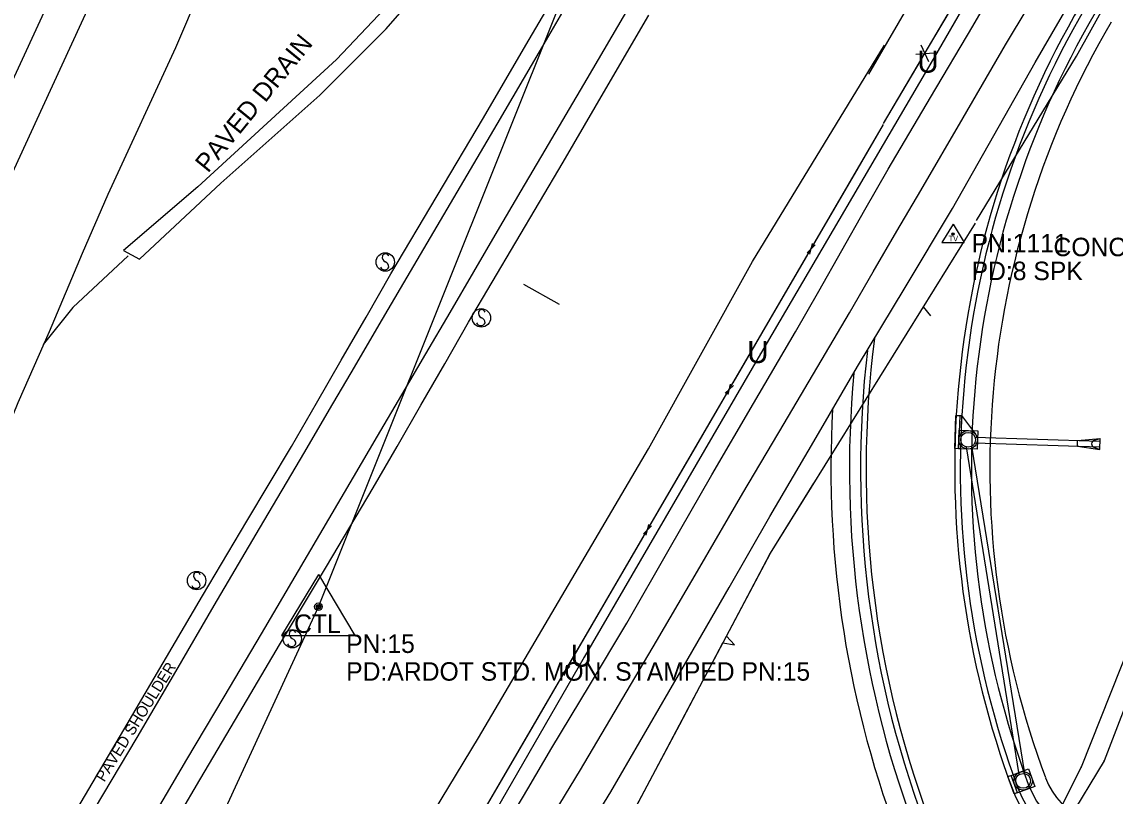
# Model space of a CAD drawing. Extents: x 978516 to 993312, y 1836504 to 1846212.
# Drawn here: x 981447.7 to 981743.5, y 1841810.9 to 1842020.4 of the extents above; entities that cross this region are included whole.
import ezdxf

# ---------------------------------------------------------------- set-up
doc = ezdxf.new("R2010")
doc.units = 0
for name, color, linetype in [('Default', 7, 'Continuous'), ('R_Drainage', 7, 'Continuous'), ('R_Proposed Road', 7, 'Continuous'), ('S_BASELINE', 7, 'Continuous'), ('S_EDGE_PAVEMENT', 7, 'Continuous'), ('S_FENCE', 7, 'Continuous'), ('S_GAS_UTILITIES', 7, 'Continuous'), ('S_PAVEMENT_CROWN', 7, 'Continuous'), ('S_PRIMARY_CTL', 7, 'Continuous'), ('S_PRIMARY_CTL_ANNOT', 7, 'Continuous'), ('S_SECONDARY_CTL', 7, 'Continuous'), ('S_SECONDARY_CTL_ANNOT', 7, 'Continuous'), ('S_SHOULDER', 7, 'Continuous'), ('S_SHOULDER_ANNOT', 7, 'Continuous'), ('S_SIDE_DRAIN_ANNOT', 7, 'Continuous'), ('S_SIGN', 7, 'Continuous'), ('S_STREAM', 7, 'Continuous'), ('S_SURVEY_TEXT_ANNOT', 7, 'Continuous'), ('S_TREE', 7, 'Continuous'), ('S_UNDERGROUND_CABLE', 7, 'Continuous'), ('S_UTL_PT_SYM', 7, 'Continuous'), ('S_WATER_UTILITIES', 7, 'Continuous')]:
    doc.layers.add(name, color=color, linetype=linetype)

msp = doc.modelspace()

# ---------------------------------------------------------------- linework, layer by layer
at = {"layer": 'R_Drainage'}
for p, q in [((981701.45, 1841913.91), (981701.16, 1841904.92)), ((981701.95, 1841913.9), (981705.74, 1841908.83)), ((981706.32, 1841909.75), (981706.16, 1841904.76)), ((981705.62, 1841908.03), (981739.42, 1841906.94)), ((981733.3, 1841905.63), (981733.35, 1841907.13)), ((981733.35, 1841907.13), (981739.45, 1841907.69)), ((981737.86, 1841907.19), (981739.45, 1841907.69)), ((981739.36, 1841904.69), (981739.45, 1841907.69)), ((981717.58, 1841816.76), (981703.29, 1841905.39)), ((981719.06, 1841817), (981704.77, 1841905.62)), ((981705.57, 1841906.53), (981739.38, 1841905.44)), ((981733.3, 1841905.63), (981739.36, 1841904.69)), ((981737.8, 1841905.3), (981739.36, 1841904.69)), ((981720.1, 1841818.26), (981721.83, 1841813.56))]:
    msp.add_line(p, q, dxfattribs=at)
for points in [[(981701.95, 1841913.9), (981701.66, 1841904.9), (981700.16, 1841904.95), (981700.45, 1841913.94)], [(981706.32, 1841909.75), (981706.16, 1841904.76), (981701.16, 1841904.92), (981701.32, 1841909.91)], [(981720.1, 1841818.26), (981721.83, 1841813.56), (981717.13, 1841811.84), (981715.41, 1841816.53)], [(981715.88, 1841816.71), (981717.6, 1841812.01), (981716.19, 1841811.5), (981714.47, 1841816.19)]]:
    msp.add_lwpolyline(points, close=True, dxfattribs=at)
for centre, radius in [((981703.74, 1841907.34), 2.5), ((981703.74, 1841907.34), 2.5), ((981703.74, 1841907.34), 2.5), ((981703.74, 1841907.34), 2), ((981703.74, 1841907.34), 2), ((981703.74, 1841907.34), 2), ((981718.62, 1841815.05), 2.5), ((981718.62, 1841815.05), 2.5), ((981718.62, 1841815.05), 2.5), ((981718.62, 1841815.05), 2), ((981718.62, 1841815.05), 2), ((981718.62, 1841815.05), 2)]:
    msp.add_circle(centre, radius, dxfattribs=at)
msp.add_arc((981738.16, 1841906.23), 1, 107.5217, 248.8077, dxfattribs=at)
at = {"layer": 'R_Proposed Road'}
for centre, radius, start, end in [((981948.55, 1841899.47), 248.44, 149.6236, 200.4683), ((981948.55, 1841899.47), 246.94, 149.6236, 200.4683), ((981948.55, 1841899.47), 243.94, 149.6236, 200.4683), ((981948.55, 1841899.47), 238.94, 149.6236, 200.4683), ((981948.55, 1841899.47), 272.44, 172.5625, 201.2591), ((981948.55, 1841899.47), 273.94, 173.2826, 201.2591), ((981948.55, 1841899.47), 276.94, 174.643, 201.2591), ((981948.55, 1841899.47), 281.94, 176.7122, 201.2591), ((981743.91, 1841823.08), 20.5, 200.4683, 289.2534), ((981743.91, 1841823.08), 30, 200.4683, 289.2534), ((981743.91, 1841823.08), 28.5, 200.4683, 289.2534), ((981743.91, 1841823.08), 25.5, 200.4683, 289.2534)]:
    msp.add_arc(centre, radius, start, end, dxfattribs=at)
at = {"layer": 'S_BASELINE'}
for p, q in [((981527.92, 1841862.16), (981778.02, 1842486.97)), ((981275.76, 1841315.9), (981527.92, 1841862.16))]:
    msp.add_line(p, q, dxfattribs=at)
at = {"layer": 'S_EDGE_PAVEMENT'}
for points in [[(981201.55, 1841475.56), (981365.38, 1841831.65), (981495.07, 1842112.92), (981495.35, 1842112.82)], [(981498.7, 1841668.6), (981509.5, 1841686.69), (981520.29, 1841704.79), (981531.16, 1841722.84), (981542.03, 1841740.88), (981553.48, 1841760.26), (981564.94, 1841779.65), (981571.48, 1841790.74), (981578.02, 1841801.83), (981584.56, 1841812.92), (981591.1, 1841824.01), (981601.25, 1841840.86), (981611.39, 1841857.72), (981622.87, 1841877.78), (981634.35, 1841897.84), (981645.68, 1841917.19), (981657.02, 1841936.53), (981663.29, 1841947.55), (981669.55, 1841958.56), (981675.82, 1841969.57), (981682.09, 1841980.59), (981693.54, 1841999.94), (981705, 1842019.29), (981716.7, 1842039.42)], [(981443.12, 1841766.2), (981449.46, 1841777.08), (981455.79, 1841787.97), (981467.32, 1841807.36), (981478.86, 1841826.76), (981489.29, 1841844.64), (981499.73, 1841862.51), (981511.98, 1841883.29), (981524.24, 1841904.07), (981530.94, 1841915.51), (981537.64, 1841926.96), (981544.35, 1841938.41), (981551.05, 1841949.85), (981563.67, 1841971.29), (981576.3, 1841992.73), (981587.7, 1842012.28), (981599.1, 1842031.84)], [(981526.44, 1841676.8), (981537.31, 1841695.08), (981547.62, 1841712.56), (981557.93, 1841730.05), (981570.05, 1841750.77), (981582.18, 1841771.5), (981594.59, 1841791.8), (981607, 1841812.11), (981617.48, 1841830.13), (981627.95, 1841848.16), (981639.03, 1841867.38), (981650.11, 1841886.61), (981661.97, 1841906.9), (981673.83, 1841927.18), (981686.69, 1841948.55), (981699.54, 1841969.91), (981710.73, 1841989.67), (981721.92, 1842009.43), (981733.83, 1842029.96)], [(981443.01, 1841736.89), (981449.38, 1841747.73), (981455.75, 1841758.57), (981462.12, 1841769.4), (981468.49, 1841780.24), (981480.39, 1841800.52), (981492.29, 1841820.79), (981502.4, 1841837.81), (981512.51, 1841854.83), (981524.95, 1841876.01), (981537.38, 1841897.18), (981543.93, 1841908.34), (981550.47, 1841919.49), (981557.02, 1841930.64), (981563.57, 1841941.79), (981569.99, 1841952.77), (981576.4, 1841963.75), (981582.82, 1841974.72), (981589.23, 1841985.7), (981600.63, 1842005.04), (981612.02, 1842024.37)]]:
    msp.add_lwpolyline(points, dxfattribs=at)
at = {"layer": 'S_FENCE'}
for p, q in [((981693.07, 1842009.56), (981691, 1842014.11)), ((981689.55, 1842011.64), (981694.53, 1842012.03)), ((981660.15, 1841957.94), (981662.38, 1841960.06)), ((981660.93, 1841957.58), (981661.59, 1841960.42)), ((981638, 1841919.93), (981640.23, 1841922.04)), ((981638.79, 1841919.56), (981639.45, 1841922.41)), ((981615.86, 1841881.91), (981618.09, 1841884.03)), ((981616.64, 1841881.55), (981617.3, 1841884.39)), ((981593.71, 1841843.9), (981595.94, 1841846.01)), ((981594.5, 1841843.53), (981595.15, 1841846.38))]:
    msp.add_line(p, q, dxfattribs=at)
for points in [[(981680.87, 1841992.89), (981817.8, 1842225.21), (981833.81, 1842251.6), (981865.94, 1842296.29), (981899.3, 1842335.3), (981936.74, 1842365.34), (981959.04, 1842379.95), (981987.1, 1842396.01)], [(981693.05, 1842013.56), (981703.21, 1842030.79)], [(981680.87, 1841992.89), (981691.02, 1842010.11)], [(981337.87, 1841409.02), (981427.3, 1841561.4), (981523.23, 1841724.55), (981572.79, 1841807.12), (981680.85, 1841992.62)], [(981672.33, 1841978.01), (981680.85, 1841992.62)], [(981662.27, 1841960.73), (981672.33, 1841978.01)], [(981650.19, 1841939.99), (981660.26, 1841957.27)], [(981640.12, 1841922.71), (981650.19, 1841939.99)], [(981628.04, 1841901.98), (981638.11, 1841919.26)], [(981617.98, 1841884.7), (981628.04, 1841901.98)], [(981605.9, 1841863.96), (981615.96, 1841881.24)], [(981595.83, 1841846.68), (981605.9, 1841863.96)], [(981583.75, 1841825.95), (981593.82, 1841843.23)], [(981573.69, 1841808.67), (981583.75, 1841825.95)]]:
    msp.add_lwpolyline(points, dxfattribs=at)
at = {"layer": 'S_GAS_UTILITIES'}
for p, q in [((981782.84, 1841931.16), (981740.59, 1841820.47)), ((981740.59, 1841820.47), (981710.07, 1841770.51))]:
    msp.add_line(p, q, dxfattribs=at)
at = {"layer": 'S_PAVEMENT_CROWN'}
msp.add_lwpolyline([(981518.44, 1841681.75), (981529.73, 1841700.01), (981539.97, 1841717.65), (981550.21, 1841735.3), (981561.83, 1841755.74), (981573.46, 1841776.19), (981586.16, 1841797.1), (981598.86, 1841818), (981609.14, 1841835.44), (981619.42, 1841852.87), (981631.1, 1841872.86), (981642.78, 1841892.85), (981653.98, 1841911.78), (981665.18, 1841930.71), (981671.61, 1841941.73), (981678.04, 1841952.75), (981684.47, 1841963.77), (981690.91, 1841974.79), (981702.37, 1841994.48), (981713.84, 1842014.17), (981725.82, 1842034.21)], dxfattribs=at)
at = {"layer": 'S_PRIMARY_CTL'}
for p, q in [((981527.92, 1841870.86), (981517.89, 1841854.34)), ((981527.92, 1841870.86), (981537.74, 1841854.34)), ((981517.89, 1841854.34), (981537.74, 1841854.34))]:
    msp.add_line(p, q, dxfattribs=at)
for radius in [1.04, 0.609, 0.344]:
    msp.add_circle((981527.92, 1841862.16), radius, dxfattribs=at)
at = {"layer": 'S_SECONDARY_CTL'}
for p, q in [((981699.67, 1841965.65), (981696.66, 1841960.7)), ((981699.67, 1841965.65), (981702.62, 1841960.7)), ((981696.66, 1841960.7), (981702.62, 1841960.7))]:
    msp.add_line(p, q, dxfattribs=at)
for radius in [0.311, 0.183, 0.103]:
    msp.add_circle((981699.67, 1841963.04), radius, dxfattribs=at)
at = {"layer": 'S_SHOULDER'}
for points in [[(981211.22, 1841472.13), (981349.29, 1841771.28), (981453.33, 1841997.41), (981503.61, 1842106.64), (981503.35, 1842106.36)], [(981445.86, 1841778.93), (981452.19, 1841789.77), (981463.7, 1841809.31), (981475.21, 1841828.84), (981485.86, 1841846.98), (981496.51, 1841865.12), (981508.56, 1841885.34), (981520.62, 1841905.56), (981527.35, 1841917.23), (981534.07, 1841928.89), (981540.8, 1841940.56), (981547.52, 1841952.22), (981560.04, 1841973.36), (981572.57, 1841994.49), (981584.05, 1842014.09), (981595.53, 1842033.69)], [(981441.77, 1841723.03), (981448.21, 1841733.96), (981454.58, 1841744.89), (981460.96, 1841755.83), (981467.33, 1841766.77), (981473.71, 1841777.71), (981484.77, 1841796.54), (981495.84, 1841815.36), (981506.62, 1841833.61), (981517.41, 1841851.87), (981530.08, 1841873.08), (981542.76, 1841894.3), (981549.2, 1841905.51), (981555.64, 1841916.72), (981562.08, 1841927.93), (981568.52, 1841939.14), (981574.93, 1841949.96), (981581.34, 1841960.78), (981587.75, 1841971.6), (981594.17, 1841982.42), (981605.73, 1842002.32), (981617.29, 1842022.22)]]:
    msp.add_lwpolyline(points, dxfattribs=at)
at = {"layer": 'S_SIGN'}
msp.add_lwpolyline([(981583.43, 1841949.41), (981593.06, 1841944.05)], dxfattribs=at)
for centre in [(981545.99, 1841955.44), (981572.02, 1841940.33), (981494.94, 1841869.25), (981520.84, 1841853.52)]:
    msp.add_circle(centre, 2.49, dxfattribs=at)
for centre, radius, start, end in [((981546.68, 1841956.77), 1.5, 167.1196, 241.9813), ((981546.07, 1841956.71), 0.95, 16.5258, 156.8957), ((981545.84, 1841954.62), 1.28, 204.641, 335.359), ((981545.58, 1841954.1), 1.4, 358.6529, 73.7063), ((981572.1, 1841941.6), 0.95, 16.5258, 156.8957), ((981572.71, 1841941.66), 1.5, 167.1196, 241.9813), ((981571.61, 1841938.99), 1.4, 358.6529, 73.7063), ((981571.87, 1841939.51), 1.28, 204.641, 335.359), ((981495.01, 1841870.52), 0.95, 16.5258, 156.8957), ((981495.62, 1841870.58), 1.5, 167.1196, 241.9813), ((981494.52, 1841867.91), 1.4, 358.6529, 73.7063), ((981494.78, 1841868.43), 1.28, 204.641, 335.359), ((981521.52, 1841854.85), 1.5, 167.1196, 241.9813), ((981520.91, 1841854.79), 0.95, 16.5258, 156.8957), ((981520.42, 1841852.18), 1.4, 358.6529, 73.7063), ((981520.68, 1841852.7), 1.28, 204.641, 335.359)]:
    msp.add_arc(centre, radius, start, end, dxfattribs=at)
at = {"layer": 'S_STREAM'}
for points in [[(981676.83, 1842006.28), (981770.93, 1842168.06), (981805.7, 1842225.16), (981835.83, 1842273.65)], [(981254.79, 1841500.45), (981296.53, 1841589.7), (981328.84, 1841654.72), (981354.48, 1841704.08), (981374.55, 1841749.89), (981390, 1841785.34), (981405.31, 1841819.83), (981414.5, 1841839.09), (981420.52, 1841852.9), (981434.91, 1841888.76), (981446.63, 1841917.45), (981455.15, 1841936.64), (981464.06, 1841957.86), (981470.97, 1841973.81), (981489.36, 1842013.45), (981509.89, 1842061.63), (981519.87, 1842083.83)], [(981584.74, 1842069.1), (981558.75, 1842037.78), (981532.83, 1842010.28), (981495.24, 1841975.79), (981475.13, 1841958.55), (981479.52, 1841956.21), (981501.48, 1841976.76), (981528.3, 1842000.56), (981546.28, 1842018.57), (981568.73, 1842044.36), (981587.93, 1842067.04), (981585.17, 1842069.21)], [(981454.48, 1841627.55), (981467.75, 1841651.82), (981485.83, 1841685.5), (981495.75, 1841699.25), (981499.5, 1841702.81), (981501.99, 1841702.63), (981505.02, 1841701.18), (981502.76, 1841702.76), (981501.9, 1841708.05), (981503.25, 1841715.47), (981509.72, 1841728.27), (981526.03, 1841754.32), (981547.19, 1841786.92), (981571.24, 1841826.68), (981617.21, 1841904.93), (981645.41, 1841955.61), (981681.15, 1842014.11)], [(981476.43, 1841957.12), (981461.43, 1841943.14), (981453.39, 1841933.13)]]:
    msp.add_lwpolyline(points, dxfattribs=at)
at = {"layer": 'S_TREE'}
for p, q in [((981693.66, 1841940.86), (981691.65, 1841943.31)), ((981640.48, 1841851.86), (981638.31, 1841854.16)), ((981637.39, 1841852.43), (981640.48, 1841851.86))]:
    msp.add_line(p, q, dxfattribs=at)
for points in [[(981706.03, 1841966.68), (981733.05, 1842011.16), (981780.76, 1842096.89), (981805.18, 1842141.89), (981834.36, 1842192.74), (981860.12, 1842238.98), (981889, 1842272.58), (981924.42, 1842309.12)], [(981766.36, 1841566.54), (981732.16, 1841579.25), (981722.29, 1841586.64), (981676.84, 1841632.71), (981649.18, 1841654.81), (981628.75, 1841673.06), (981604.57, 1841695.11), (981584.43, 1841716.37), (981580.14, 1841728.92), (981583.94, 1841748.19), (981610.45, 1841801.62), (981650.25, 1841876.7), (981705.73, 1841965.97)], [(981650.02, 1841876.25), (981650.25, 1841876.7), (981661.99, 1841895.58)], [(981638.31, 1841854.16), (981650.02, 1841876.25)], [(981625.68, 1841830.34), (981637.39, 1841852.43)], [(981613.97, 1841808.25), (981625.68, 1841830.34)]]:
    msp.add_lwpolyline(points, dxfattribs=at)
at = {"layer": 'S_UNDERGROUND_CABLE'}
for p, q in [((981740.95, 1842091.42), (981693.62, 1842009.22)), ((981693.62, 1842009.22), (981647.57, 1841930.63)), ((981647.57, 1841930.63), (981599.8, 1841848.48)), ((981599.8, 1841848.48), (981554.31, 1841769.52))]:
    msp.add_line(p, q, dxfattribs=at)
at = {"layer": 'S_UTL_PT_SYM'}
for points in [[(981693.62, 1842009.22), (981693.62, 1842009.27), (981693.62, 1842009.22), (981693.57, 1842009.22), (981693.62, 1842009.22), (981693.62, 1842009.17), (981693.62, 1842009.22), (981693.67, 1842009.22)], [(981647.57, 1841930.63), (981647.57, 1841930.68), (981647.57, 1841930.63), (981647.52, 1841930.63), (981647.57, 1841930.63), (981647.57, 1841930.58), (981647.57, 1841930.63), (981647.62, 1841930.63)], [(981599.8, 1841848.48), (981599.8, 1841848.53), (981599.8, 1841848.48), (981599.75, 1841848.48), (981599.8, 1841848.48), (981599.8, 1841848.43), (981599.8, 1841848.48), (981599.85, 1841848.48)], [(981734.32, 1841818.76), (981734.32, 1841818.81), (981734.32, 1841818.76), (981734.27, 1841818.76), (981734.32, 1841818.76), (981734.32, 1841818.71), (981734.32, 1841818.76), (981734.37, 1841818.76)], [(981740.59, 1841820.47), (981740.59, 1841820.52), (981740.59, 1841820.47), (981740.54, 1841820.47), (981740.59, 1841820.47), (981740.59, 1841820.42), (981740.59, 1841820.47), (981740.64, 1841820.47)]]:
    msp.add_lwpolyline(points, dxfattribs=at)
at = {"layer": 'S_WATER_UTILITIES'}
for p, q in [((981774.57, 1841920.32), (981734.32, 1841818.76)), ((981734.32, 1841818.76), (981710.07, 1841770.51))]:
    msp.add_line(p, q, dxfattribs=at)

# ---------------------------------------------------------------- texts
at = {"layer": 'Default'}
for p in [(981689.99, 1842006.67), (981643.94, 1841928.09), (981596.17, 1841845.93)]:
    msp.add_text('U', height=6, dxfattribs=at).set_placement(p)
at = {"layer": 'S_PRIMARY_CTL'}
msp.add_text('CTL', height=5, dxfattribs=at).set_placement((981521.33, 1841855.08))
at = {"layer": 'S_PRIMARY_CTL_ANNOT'}
for s, p in [('PN:15', (981535.42, 1841849.66)), ('PD:ARDOT STD. MON. STAMPED PN:15', (981535.42, 1841842.16))]:
    msp.add_text(s, height=5, dxfattribs=at).set_placement(p)
at = {"layer": 'S_SECONDARY_CTL'}
msp.add_text('TV', height=1.5, dxfattribs=at).set_placement((981698.46, 1841961.03))
at = {"layer": 'S_SECONDARY_CTL_ANNOT'}
for s, p in [('PN:1111', (981704.67, 1841958.04)), ('PD:8 SPK', (981704.67, 1841950.54))]:
    msp.add_text(s, height=5, dxfattribs=at).set_placement(p)
at = {"layer": 'S_SHOULDER_ANNOT'}
msp.add_text('PAVED SHOULDER', height=3.0003, rotation=58.0702, dxfattribs=at).set_placement((981469.95, 1841814.55))
at = {"layer": 'S_SIDE_DRAIN_ANNOT'}
msp.add_text('PAVED DRAIN', height=5.0005, rotation=50.8238, dxfattribs=at).set_placement((981498.02, 1841979.33))
at = {"layer": 'S_SURVEY_TEXT_ANNOT'}
msp.add_text('CONC DL', height=5, dxfattribs=at).set_placement((981726.83, 1841957.01))

doc.saveas('drawing.dxf')
